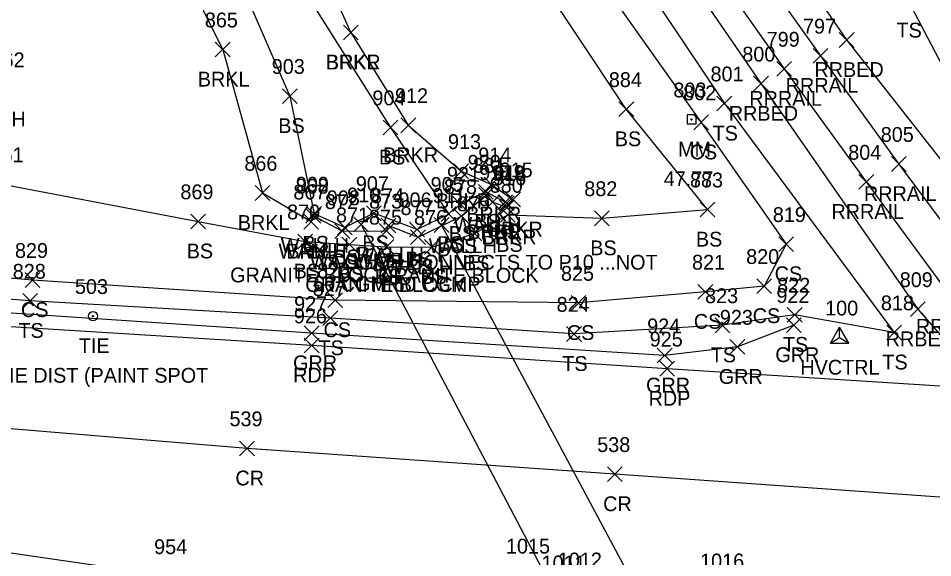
# Model space of a CAD drawing. Extents: x 1679360 to 1685861, y 903420 to 905946.
# Drawn here: x 1679676.5 to 1679800, y 904022.2 to 904095.2 of the extents above; entities that cross this region are included whole.
import ezdxf

# ---------------------------------------------------------------- set-up
doc = ezdxf.new("R2010")
doc.units = 0
for name, color, linetype in [('C_A', 7, 'Continuous'), ('C_C', 7, 'Continuous'), ('C_I', 7, 'Continuous'), ('CBP', 7, 'Continuous'), ('CPSM', 7, 'Continuous'), ('D_A', 7, 'Continuous'), ('D_C', 7, 'Continuous'), ('D_I', 7, 'Continuous'), ('D_TIC', 7, 'Continuous'), ('DCP', 7, 'Continuous'), ('DHW', 7, 'Continuous'), ('L_A', 7, 'Continuous'), ('L_I', 7, 'Continuous'), ('L_TIC', 7, 'Continuous'), ('LAWE', 7, 'Continuous'), ('LELB', 7, 'Continuous'), ('P_A', 7, 'Continuous'), ('P_I', 7, 'Continuous'), ('P_TIC', 7, 'Continuous'), ('PET', 7, 'Continuous'), ('PRC', 7, 'Continuous'), ('R_A', 7, 'Continuous'), ('R_I', 7, 'Continuous'), ('R_TIC', 7, 'Continuous'), ('RGR', 7, 'Continuous'), ('RR', 7, 'Continuous'), ('RRB', 7, 'Continuous'), ('S_A', 7, 'Continuous'), ('S_C', 7, 'Continuous'), ('S_I', 7, 'Continuous'), ('SRM', 7, 'Continuous')]:
    doc.layers.add(name, color=color, linetype=linetype)

msp = doc.modelspace()

# ---------------------------------------------------------------- linework, layer by layer
at = {"layer": 'CBP'}
for radius in [0.625, 0.0833]:
    msp.add_circle((1679686.58, 904054.87), radius, dxfattribs=at)
at = {"layer": 'CPSM'}
for p, q in [((1679786.2, 904051.23), (1679787.45, 904053.4)), ((1679788.7, 904051.23), (1679787.45, 904053.4)), ((1679787.45, 904051.96), (1679787.45, 904053.4)), ((1679786.2, 904051.23), (1679787.45, 904051.96)), ((1679786.2, 904051.23), (1679788.7, 904051.23)), ((1679787.45, 904051.96), (1679787.45, 904051.96)), ((1679787.45, 904051.96), (1679788.7, 904051.23))]:
    msp.add_line(p, q, dxfattribs=at)
at = {"layer": 'D_TIC'}
for points in [[(1679738.7, 904070.26), (1679740.7, 904072.26)], [(1679740.7, 904070.26), (1679738.7, 904072.26)], [(1679741.48, 904069.16), (1679743.48, 904071.16)], [(1679743.48, 904069.16), (1679741.48, 904071.16)], [(1679715.35, 904067.44), (1679717.35, 904069.44)], [(1679717.35, 904067.44), (1679715.35, 904069.44)], [(1679735.35, 904067.39), (1679737.35, 904069.39)], [(1679737.35, 904067.39), (1679735.35, 904069.39)], [(1679715.06, 904066.65), (1679717.06, 904068.65)], [(1679717.06, 904066.65), (1679715.06, 904068.65)], [(1679721.81, 904066.25), (1679723.81, 904068.25)], [(1679723.81, 904066.25), (1679721.81, 904068.25)], [(1679725.5, 904066.14), (1679727.5, 904068.14)], [(1679727.5, 904066.14), (1679725.5, 904068.14)], [(1679732.68, 904066.19), (1679734.68, 904068.19)], [(1679734.68, 904066.19), (1679732.68, 904068.19)], [(1679719.27, 904065.35), (1679721.27, 904067.35)], [(1679721.27, 904065.35), (1679719.27, 904067.35)], [(1679725.24, 904065.41), (1679727.24, 904067.41)], [(1679727.24, 904065.41), (1679725.24, 904067.41)], [(1679729.49, 904064.54), (1679731.49, 904066.54)], [(1679731.49, 904064.54), (1679729.49, 904066.54)]]:
    msp.add_lwpolyline(points, dxfattribs=at)
at = {"layer": 'DCP'}
for points in [[(1679722.81, 904067.25), (1679756.53, 904002.99)], [(1679733.68, 904067.19), (1679768.04, 904002.96)]]:
    msp.add_lwpolyline(points, dxfattribs=at)
at = {"layer": 'DHW'}
for points in [[(1679736.35, 904068.39), (1679739.7, 904071.26)], [(1679716.06, 904067.65), (1679716.35, 904068.44), (1679720.27, 904066.35)], [(1679726.24, 904066.41), (1679726.5, 904067.14), (1679730.49, 904065.54)]]:
    msp.add_lwpolyline(points, dxfattribs=at)
at = {"layer": 'L_TIC'}
for points in [[(1679720.41, 904092.23), (1679722.41, 904094.23)], [(1679722.41, 904092.23), (1679720.41, 904094.23)], [(1679720.41, 904092.23), (1679722.41, 904094.23)], [(1679722.41, 904092.23), (1679720.41, 904094.23)], [(1679703.1, 904089.92), (1679705.1, 904091.92)], [(1679705.1, 904089.92), (1679703.1, 904091.92)], [(1679712.17, 904083.63), (1679714.17, 904085.63)], [(1679714.17, 904083.63), (1679712.17, 904085.63)], [(1679770.88, 904082.62), (1679772.88, 904084.62)], [(1679772.88, 904082.62), (1679770.88, 904084.62)], [(1679757.63, 904081.85), (1679759.63, 904083.85)], [(1679759.63, 904081.85), (1679757.63, 904083.85)], [(1679728.18, 904079.68), (1679730.18, 904081.68)], [(1679730.18, 904079.68), (1679728.18, 904081.68)], [(1679767.75, 904080.07), (1679769.75, 904082.07)], [(1679769.75, 904080.07), (1679767.75, 904082.07)], [(1679725.77, 904079.38), (1679727.77, 904081.38)], [(1679727.77, 904079.38), (1679725.77, 904081.38)], [(1679735.33, 904073.46), (1679737.33, 904075.46)], [(1679737.33, 904073.46), (1679735.33, 904075.46)], [(1679739.42, 904071.67), (1679741.42, 904073.67)], [(1679741.42, 904071.67), (1679739.42, 904073.67)], [(1679708.49, 904070.53), (1679710.49, 904072.53)], [(1679710.49, 904070.53), (1679708.49, 904072.53)], [(1679738.65, 904070.68), (1679740.65, 904072.68)], [(1679740.65, 904070.68), (1679738.65, 904072.68)], [(1679735.2, 904069.04), (1679737.2, 904071.04)], [(1679737.2, 904069.04), (1679735.2, 904071.04)], [(1679739.55, 904069.27), (1679741.55, 904071.27)], [(1679741.55, 904069.27), (1679739.55, 904071.27)], [(1679741.25, 904069.27), (1679743.25, 904071.27)], [(1679743.25, 904069.27), (1679741.25, 904071.27)], [(1679741.48, 904068.57), (1679743.48, 904070.57)], [(1679743.48, 904068.57), (1679741.48, 904070.57)], [(1679742.32, 904069.64), (1679744.32, 904071.64)], [(1679744.32, 904069.64), (1679742.32, 904071.64)], [(1679715.44, 904067.71), (1679717.44, 904069.71)], [(1679717.44, 904067.71), (1679715.44, 904069.71)], [(1679715.44, 904067.71), (1679717.44, 904069.71)], [(1679717.44, 904067.71), (1679715.44, 904069.71)], [(1679723.53, 904067.78), (1679725.53, 904069.78)], [(1679725.53, 904067.78), (1679723.53, 904069.78)], [(1679733.63, 904067.68), (1679735.63, 904069.68)], [(1679735.63, 904067.68), (1679733.63, 904069.68)], [(1679735.35, 904067.39), (1679737.35, 904069.39)], [(1679737.35, 904067.39), (1679735.35, 904069.39)], [(1679741.62, 904067.56), (1679743.62, 904069.56)], [(1679743.62, 904067.56), (1679741.62, 904069.56)], [(1679768.59, 904068.28), (1679770.59, 904070.28)], [(1679770.59, 904068.28), (1679768.59, 904070.28)], [(1679699.8, 904066.68), (1679701.8, 904068.68)], [(1679701.8, 904066.68), (1679699.8, 904068.68)], [(1679715.06, 904066.65), (1679717.06, 904068.65)], [(1679717.06, 904066.65), (1679715.06, 904068.65)], [(1679754.32, 904067.1), (1679756.32, 904069.1)], [(1679756.32, 904067.1), (1679754.32, 904069.1)], [(1679719.27, 904065.35), (1679721.27, 904067.35)], [(1679721.27, 904065.35), (1679719.27, 904067.35)], [(1679719.61, 904065.87), (1679721.61, 904067.87)], [(1679721.61, 904065.87), (1679719.61, 904067.87)], [(1679725.24, 904065.41), (1679727.24, 904067.41)], [(1679727.24, 904065.41), (1679725.24, 904067.41)], [(1679729.36, 904065.6), (1679731.36, 904067.6)], [(1679731.36, 904065.6), (1679729.36, 904067.6)], [(1679737.12, 904065.05), (1679739.12, 904067.05)], [(1679739.12, 904065.05), (1679737.12, 904067.05)], [(1679714.25, 904063.96), (1679716.25, 904065.96)], [(1679716.25, 904063.96), (1679714.25, 904065.96)], [(1679729.49, 904064.54), (1679731.49, 904066.54)], [(1679731.49, 904064.54), (1679729.49, 904066.54)], [(1679779.23, 904063.6), (1679781.23, 904065.6)], [(1679781.23, 904063.6), (1679779.23, 904065.6)], [(1679720.21, 904063.56), (1679722.21, 904065.56)], [(1679722.21, 904063.56), (1679720.21, 904065.56)], [(1679725.22, 904063.25), (1679727.22, 904065.25)], [(1679727.22, 904063.25), (1679725.22, 904065.25)], [(1679731.36, 904063.22), (1679733.36, 904065.22)], [(1679733.36, 904063.22), (1679731.36, 904065.22)], [(1679677.41, 904058.75), (1679679.41, 904060.75)], [(1679679.41, 904058.75), (1679677.41, 904060.75)], [(1679776.26, 904057.93), (1679778.26, 904059.93)], [(1679778.26, 904057.93), (1679776.26, 904059.93)], [(1679768.31, 904057.16), (1679770.31, 904059.16)], [(1679770.31, 904057.16), (1679768.31, 904059.16)], [(1679677.1, 904055.93), (1679679.1, 904057.93)], [(1679679.1, 904055.93), (1679677.1, 904057.93)], [(1679718.29, 904056.03), (1679720.29, 904058.03)], [(1679720.29, 904056.03), (1679718.29, 904058.03)], [(1679751.16, 904055.65), (1679753.16, 904057.65)], [(1679753.16, 904055.65), (1679751.16, 904057.65)], [(1679780.37, 904054.05), (1679782.37, 904056.05)], [(1679782.37, 904054.05), (1679780.37, 904056.05)], [(1679717.64, 904053.59), (1679719.64, 904055.59)], [(1679719.64, 904053.59), (1679717.64, 904055.59)], [(1679770.63, 904052.63), (1679772.63, 904054.63)], [(1679772.63, 904052.63), (1679770.63, 904054.63)], [(1679750.57, 904051.46), (1679752.57, 904053.46)], [(1679752.57, 904051.46), (1679750.57, 904053.46)], [(1679793.81, 904051.66), (1679795.81, 904053.66)], [(1679795.81, 904051.66), (1679793.81, 904053.66)]]:
    msp.add_lwpolyline(points, dxfattribs=at)
at = {"layer": 'LAWE'}
for points in [[(1679721.41, 904093.23), (1679710.28, 904118.26), (1679642.61, 904214.69), (1679624.73, 904243.46), (1679599.05, 904283.15), (1679584.74, 904306.73)], [(1679693.3, 904112.54), (1679704.1, 904090.92), (1679709.49, 904071.53), (1679716.06, 904067.65)], [(1679721.41, 904093.23), (1679729.18, 904080.68), (1679736.33, 904074.46), (1679740.42, 904072.67), (1679743.32, 904070.64), (1679742.48, 904069.57), (1679740.55, 904070.27)]]:
    msp.add_lwpolyline(points, dxfattribs=at)
at = {"layer": 'LELB'}
for points in [[(1679957.35, 904067.57), (1679950.7, 904052.36), (1679948.48, 904046.41), (1679946.09, 904041.57), (1679931.01, 904039.98), (1679888.72, 904042.9), (1679856.91, 904046.05), (1679830.24, 904050.06), (1679823.69, 904055.74), (1679818.78, 904061.51), (1679813.5, 904065.59), (1679796.72, 904097.55), (1679771.59, 904129.9), (1679746.93, 904164.44), (1679719.12, 904199.21), (1679701.21, 904226.94), (1679680.19, 904259.65), (1679656.34, 904293.81), (1679636.23, 904329.88)], [(1679619.82, 904321.42), (1679641.86, 904284.96), (1679662.72, 904251.2), (1679682.47, 904216.95), (1679699.46, 904186.97), (1679725.72, 904150), (1679749.74, 904116.77), (1679771.88, 904083.62), (1679794.81, 904052.66), (1679781.37, 904055.05), (1679771.63, 904053.63), (1679751.57, 904052.46), (1679718.64, 904054.59), (1679678.1, 904056.93), (1679638.82, 904059.88), (1679596.67, 904062.24), (1679555.45, 904065.45), (1679516.04, 904068.29), (1679469.12, 904071.92)], [(1679613.72, 904318.48), (1679636.27, 904281.99), (1679658.68, 904248.53), (1679679.07, 904215.01), (1679696.37, 904185.6), (1679721.82, 904147.6), (1679745.3, 904114.19), (1679768.75, 904081.07), (1679780.23, 904064.6), (1679777.26, 904058.93), (1679769.31, 904058.16), (1679752.16, 904056.65), (1679719.29, 904057.03), (1679678.41, 904059.75), (1679639.22, 904063.11), (1679596.82, 904065.62), (1679556, 904068.19), (1679515.9, 904070.74), (1679469.14, 904074.52)], [(1679469.87, 904080.86), (1679506.34, 904080.86), (1679543.9, 904078.61), (1679576.91, 904079.34), (1679615.93, 904077.92), (1679644, 904075.64), (1679674.59, 904072.69), (1679700.8, 904067.68), (1679715.25, 904064.96), (1679721.21, 904064.56), (1679726.22, 904064.25), (1679732.36, 904064.22), (1679738.12, 904066.05), (1679742.62, 904068.56), (1679755.32, 904068.1), (1679769.59, 904069.28), (1679758.63, 904082.85), (1679744.91, 904103.49), (1679726.51, 904128.69), (1679708.52, 904157.77), (1679684.84, 904191.6)], [(1679704.38, 904115.88), (1679726.77, 904080.38), (1679734.63, 904068.68), (1679730.36, 904066.6), (1679724.53, 904068.78), (1679720.61, 904066.87), (1679716.44, 904068.71)], [(1679700.75, 904113.26), (1679713.17, 904084.63), (1679716.44, 904068.71)], [(1679742.25, 904070.27), (1679739.65, 904071.68), (1679736.2, 904070.04)], [(1679730.49, 904065.54), (1679736.35, 904068.39)], [(1679720.27, 904066.35), (1679726.24, 904066.41)]]:
    msp.add_lwpolyline(points, dxfattribs=at)
at = {"layer": 'P_TIC'}
for points in [[(1679715.13, 904049.9), (1679717.13, 904051.9)], [(1679717.13, 904049.9), (1679715.13, 904051.9)], [(1679763.15, 904046.76), (1679765.15, 904048.76)], [(1679765.15, 904046.76), (1679763.15, 904048.76)], [(1679706.39, 904035.98), (1679708.39, 904037.98)], [(1679708.39, 904035.98), (1679706.39, 904037.98)], [(1679756.07, 904032.5), (1679758.07, 904034.5)], [(1679758.07, 904032.5), (1679756.07, 904034.5)]]:
    msp.add_lwpolyline(points, dxfattribs=at)
at = {"layer": 'PET'}
for points in [[(1680210.84, 904017.73), (1680154.55, 904022.58), (1680102.27, 904026.43), (1680051.74, 904029.42), (1680001.13, 904032.43), (1679941.04, 904036.26), (1679894.06, 904039.28), (1679848.46, 904042.23), (1679824.08, 904043.91), (1679814.8, 904045.29), (1679808.83, 904044.91), (1679764.15, 904047.76), (1679716.13, 904050.9), (1679671, 904053.69), (1679626.09, 904056.57), (1679579.85, 904059.36), (1679535.31, 904061.44), (1679496.62, 904064.3), (1679468.44, 904066.43)], [(1679464.45, 904041.77), (1679494.85, 904039.78), (1679533.66, 904036.86), (1679564.76, 904034.75), (1679595.94, 904030.8), (1679627.79, 904028.13), (1679661.16, 904024.92), (1679697.2, 904019.69), (1679719.42, 904015.4), (1679737.48, 904014.62), (1679744.58, 904019.77), (1679770.86, 904017.76), (1679789.63, 904016.53)]]:
    msp.add_lwpolyline(points, dxfattribs=at)
at = {"layer": 'PRC'}
msp.add_lwpolyline([(1680209.65, 904002.04), (1680152.97, 904005.78), (1680100.29, 904009.57), (1680049.21, 904012.91), (1679999.46, 904016.39), (1679940.5, 904020.99), (1679893.64, 904024.04), (1679847.03, 904027.44), (1679827.53, 904028.69), (1679808.61, 904029.86), (1679757.07, 904033.5), (1679707.39, 904036.98), (1679666.22, 904040.39), (1679623.03, 904043.25), (1679581.59, 904046.25), (1679534.87, 904049.67), (1679494.87, 904052.55), (1679467.34, 904054.68)], dxfattribs=at)
at = {"layer": 'R_TIC'}
for points in [[(1679787.39, 904091.22), (1679789.39, 904093.22)], [(1679789.39, 904091.22), (1679787.39, 904093.22)], [(1679783.87, 904089.08), (1679785.87, 904091.08)], [(1679785.87, 904089.08), (1679783.87, 904091.08)], [(1679778.96, 904087.31), (1679780.96, 904089.31)], [(1679780.96, 904087.31), (1679778.96, 904089.31)], [(1679775.83, 904085.3), (1679777.83, 904087.3)], [(1679777.83, 904085.3), (1679775.83, 904087.3)], [(1679794.44, 904074.44), (1679796.44, 904076.44)], [(1679796.44, 904074.44), (1679794.44, 904076.44)], [(1679790.05, 904072.02), (1679792.05, 904074.02)], [(1679792.05, 904072.02), (1679790.05, 904074.02)], [(1679797.02, 904054.8), (1679799.02, 904056.8)], [(1679799.02, 904054.8), (1679797.02, 904056.8)], [(1679780.27, 904052.66), (1679782.27, 904054.66)], [(1679782.27, 904052.66), (1679780.27, 904054.66)], [(1679715.12, 904051.56), (1679717.12, 904053.56)], [(1679717.12, 904051.56), (1679715.12, 904053.56)], [(1679772.63, 904049.71), (1679774.63, 904051.71)], [(1679774.63, 904049.71), (1679772.63, 904051.71)], [(1679762.81, 904048.54), (1679764.81, 904050.54)], [(1679764.81, 904048.54), (1679762.81, 904050.54)]]:
    msp.add_lwpolyline(points, dxfattribs=at)
at = {"layer": 'RGR'}
msp.add_lwpolyline([(1679781.27, 904053.66), (1679773.63, 904050.71), (1679763.81, 904049.54), (1679716.12, 904052.56), (1679671.48, 904055.53), (1679626.4, 904058.62), (1679580.17, 904061.85), (1679535.72, 904064.7), (1679497.22, 904067.59), (1679469, 904069.72)], dxfattribs=at)
at = {"layer": 'RR'}
for points in [[(1679726.81, 904174.45), (1679738.46, 904156.9), (1679751.84, 904137.33), (1679761.54, 904123.21), (1679774.27, 904104.96), (1679784.87, 904090.08), (1679795.44, 904075.44), (1679806.42, 904060.67), (1679817.7, 904045.88), (1679831.29, 904028.45), (1679844.1, 904012.06)], [(1679722.86, 904171.49), (1679733.8, 904154.92), (1679747.61, 904134.64), (1679756.68, 904121.56), (1679770.36, 904101.93), (1679779.96, 904088.31), (1679791.05, 904073.02), (1679802.46, 904057.5), (1679811.73, 904045.41), (1679824.64, 904028.72), (1679837.34, 904012.39)]]:
    msp.add_lwpolyline(points, dxfattribs=at)
at = {"layer": 'RRB'}
for points in [[(1679633.2, 904329.89), (1679656.09, 904293.31), (1679676.78, 904259.06), (1679698.16, 904224.73), (1679716.55, 904197.16), (1679742.3, 904159.89), (1679765.39, 904125.58), (1679788.39, 904092.22), (1679811.33, 904062.99), (1679819.97, 904050.18)], [(1679622.51, 904322.69), (1679644.95, 904286.47), (1679665.07, 904252.34), (1679687.42, 904219.26), (1679705.66, 904190.77), (1679730.04, 904152.75), (1679754.13, 904119.39), (1679776.83, 904086.3), (1679798.02, 904055.8), (1679804.41, 904048.47)]]:
    msp.add_lwpolyline(points, dxfattribs=at)
at = {"layer": 'SRM'}
for p, q in [((1679768.08, 904082.11), (1679766.83, 904082.11)), ((1679766.83, 904082.11), (1679766.83, 904080.86)), ((1679768.08, 904082.11), (1679766.83, 904082.11)), ((1679766.83, 904082.11), (1679766.83, 904080.86)), ((1679768.08, 904080.86), (1679768.08, 904082.11)), ((1679768.08, 904080.86), (1679768.08, 904082.11)), ((1679766.83, 904080.86), (1679768.08, 904080.86)), ((1679766.83, 904080.86), (1679768.08, 904080.86))]:
    msp.add_line(p, q, dxfattribs=at)
msp.add_circle((1679767.43, 904081.45), 0.0833, dxfattribs=at)

# ---------------------------------------------------------------- texts
at = {"layer": 'C_A'}
for s, p in [('TIE', (1679684.66, 904049.87)), ('HVCTRL', (1679782.14, 904046.96))]:
    msp.add_text(s, height=2, dxfattribs=at).set_placement(p)
at = {"layer": 'C_C'}
msp.add_text('46.53 IS TIE DIST (PAINT SPOT', height=2, dxfattribs=at).set_placement((1679662.91, 904045.87))
at = {"layer": 'C_I'}
for s, p in [('503', (1679684.14, 904057.87)), ('100', (1679785.49, 904054.96))]:
    msp.add_text(s, height=2, dxfattribs=at).set_placement(p)
at = {"layer": 'D_A'}
for s, p in [('WALLH', (1679735.29, 904066.26)), ('P', (1679741.86, 904065.16)), ('WALLH', (1679711.65, 904062.65)), ('WALLH', (1679711.95, 904063.44)), ('WALLH', (1679731.94, 904063.39)), ('WALLH', (1679715.86, 904061.35)), ('WALLH', (1679721.83, 904061.41)), ('WALLH', (1679722.09, 904062.14)), ('P', (1679722.18, 904062.25)), ('P', (1679733.06, 904062.19)), ('WALLH', (1679726.08, 904060.54))]:
    msp.add_text(s, height=2, dxfattribs=at).set_placement(p)
at = {"layer": 'D_C'}
for s, p in [('18 CGMP CONNECTS TO P10 ...NOT', (1679716.79, 904061.16)), ('GRANITE BLOCK', (1679705.11, 904059.44)), ('GRANITE BLOCK', (1679725.1, 904059.39)), ('GRANITE BLOCK', (1679715.26, 904058.14)), ('60 CGMP', (1679716.33, 904058.25)), ('60 CGMP', (1679727.2, 904058.19))]:
    msp.add_text(s, height=2, dxfattribs=at).set_placement(p)
at = {"layer": 'D_I'}
for s, p in [('881', (1679737.9, 904074.26)), ('918', (1679740.68, 904073.16)), ('868', (1679713.95, 904071.44)), ('878', (1679733.99, 904071.39)), ('867', (1679713.65, 904070.65)), ('910', (1679720.92, 904070.25)), ('874', (1679724.14, 904070.14)), ('911', (1679732.46, 904070.19)), ('872', (1679717.91, 904069.35)), ('873', (1679723.88, 904069.41)), ('877', (1679728.13, 904068.54))]:
    msp.add_text(s, height=2, dxfattribs=at).set_placement(p)
at = {"layer": 'L_A'}
for s, p in [('TS', (1679795.13, 904092.55)), ('BRKR', (1679718, 904088.23)), ('BRKL', (1679718.06, 904088.23)), ('BRKL', (1679700.74, 904085.92)), ('SH', (1679673.77, 904080.53)), ('BS', (1679711.61, 904079.63)), ('TS', (1679770.29, 904078.62)), ('BS', (1679757.07, 904077.85)), ('CS', (1679767.19, 904076.07)), ('BS', (1679725.21, 904075.38)), ('BRKR', (1679725.77, 904075.68)), ('BRKR', (1679732.92, 904069.46)), ('BRKR', (1679737.01, 904067.67)), ('BRKL', (1679706.14, 904066.53)), ('BS', (1679738.09, 904066.68)), ('BS', (1679734.64, 904065.04)), ('BRKR', (1679737.14, 904065.27)), ('BRKR', (1679739.91, 904065.64)), ('BS', (1679740.69, 904065.27)), ('BS', (1679714.88, 904063.71)), ('BS', (1679714.88, 904063.71)), ('BS', (1679722.97, 904063.78)), ('BS', (1679733.07, 904063.68)), ('BRKR', (1679739.07, 904064.57)), ('BS', (1679768.03, 904064.28)), ('BS', (1679699.24, 904062.68)), ('BRKL', (1679712.7, 904062.65)), ('CS', (1679734.79, 904063.39)), ('BS', (1679741.06, 904063.56)), ('BS', (1679753.76, 904063.1)), ('CS', (1679718.71, 904061.35)), ('BS', (1679719.05, 904061.87)), ('CS', (1679724.68, 904061.41)), ('BS', (1679728.8, 904061.6)), ('BS', (1679713.69, 904059.96)), ('CS', (1679728.93, 904060.54)), ('BS', (1679736.56, 904061.05)), ('BS', (1679719.65, 904059.56)), ('BS', (1679724.66, 904059.25)), ('BS', (1679730.8, 904059.22)), ('CS', (1679778.67, 904059.6)), ('CS', (1679676.85, 904054.75)), ('CS', (1679775.71, 904053.93)), ('CS', (1679767.75, 904053.16)), ('TS', (1679676.51, 904051.93)), ('CS', (1679717.73, 904052.03)), ('CS', (1679750.6, 904051.65)), ('TS', (1679779.78, 904050.05)), ('TS', (1679717.05, 904049.59)), ('TS', (1679770.04, 904048.63)), ('TS', (1679793.22, 904047.66)), ('TS', (1679749.98, 904047.46))]:
    msp.add_text(s, height=2, dxfattribs=at).set_placement(p)
at = {"layer": 'L_I'}
for s, p in [('865', (1679701.69, 904093.92)), ('862', (1679672.88, 904088.53)), ('903', (1679710.73, 904087.63)), ('884', (1679756.27, 904085.85)), ('801', (1679770.01, 904086.62)), ('904', (1679724.33, 904083.38)), ('912', (1679727.38, 904083.68)), ('802', (1679766.31, 904084.07)), ('913', (1679734.54, 904077.46)), ('861', (1679672.74, 904075.69)), ('920', (1679737.2, 904074.68)), ('914', (1679738.63, 904075.67)), ('866', (1679707.03, 904074.53)), ('915', (1679741.52, 904073.64)), ('921', (1679734.4, 904073.04)), ('917', (1679738.76, 904073.27)), ('919', (1679740.44, 904073.27)), ('916', (1679740.63, 904072.57)), ('883', (1679767.23, 904072.28)), ('909', (1679713.99, 904071.71)), ('909', (1679713.99, 904071.71)), ('907', (1679722.09, 904071.78)), ('905', (1679732.19, 904071.68)), ('878', (1679733.99, 904071.39)), ('880', (1679740.17, 904071.56)), ('882', (1679752.95, 904071.1)), ('869', (1679698.39, 904070.68)), ('867', (1679713.65, 904070.65)), ('908', (1679718.17, 904069.87)), ('872', (1679717.91, 904069.35)), ('873', (1679723.88, 904069.41)), ('906', (1679727.86, 904069.6)), ('877', (1679728.13, 904068.54)), ('879', (1679735.75, 904069.05)), ('870', (1679712.8, 904067.96)), ('871', (1679719.41, 904067.56)), ('819', (1679778.42, 904067.6)), ('875', (1679723.86, 904067.25)), ('876', (1679729.95, 904067.22)), ('829', (1679676.04, 904062.75)), ('821', (1679767.51, 904061.16)), ('820', (1679774.82, 904061.93)), ('828', (1679675.74, 904059.93)), ('826', (1679716.87, 904060.03)), ('825', (1679749.8, 904059.65)), ('827', (1679716.27, 904057.59)), ('822', (1679779.01, 904058.05)), ('823', (1679769.27, 904056.63)), ('824', (1679749.21, 904055.46)), ('818', (1679793.02, 904055.66))]:
    msp.add_text(s, height=2, dxfattribs=at).set_placement(p)
at = {"layer": 'P_A'}
for s, p in [('RDP', (1679713.62, 904045.9)), ('RDP', (1679761.64, 904042.76)), ('CR', (1679705.82, 904031.98)), ('CR', (1679755.5, 904028.5))]:
    msp.add_text(s, height=2, dxfattribs=at).set_placement(p)
at = {"layer": 'P_I'}
for s, p in [('926', (1679713.72, 904053.9)), ('925', (1679761.79, 904050.76)), ('539', (1679705.02, 904039.98)), ('538', (1679754.7, 904036.5)), ('954', (1679694.84, 904022.69)), ('1015', (1679742.37, 904022.77)), ('1016', (1679768.6, 904020.76))]:
    msp.add_text(s, height=2, dxfattribs=at).set_placement(p)
at = {"layer": 'R_A'}
for s, p in [('RRBED', (1679784.04, 904087.22)), ('RRRAIL', (1679780.16, 904085.08)), ('RRRAIL', (1679775.25, 904083.31)), ('RRBED', (1679772.47, 904081.3)), ('RRRAIL', (1679790.73, 904070.44)), ('RRRAIL', (1679786.34, 904068.02)), ('RRRAIL', (1679797.75, 904052.5)), ('RRBED', (1679793.67, 904050.8)), ('GRR', (1679713.61, 904047.56)), ('GRR', (1679778.76, 904048.66)), ('GRR', (1679771.12, 904045.71)), ('GRR', (1679761.3, 904044.54))]:
    msp.add_text(s, height=2, dxfattribs=at).set_placement(p)
at = {"layer": 'R_I'}
for s, p in [('797', (1679782.5, 904093.08)), ('799', (1679777.59, 904091.31)), ('800', (1679774.3, 904089.3)), ('805', (1679793, 904078.44)), ('804', (1679788.61, 904076.02)), ('809', (1679795.57, 904058.8)), ('922', (1679778.91, 904056.66)), ('927', (1679713.75, 904055.56)), ('923', (1679771.27, 904053.71)), ('924', (1679761.45, 904052.54)), ('1011', (1679747.18, 904020.49)), ('1012', (1679749.38, 904020.89))]:
    msp.add_text(s, height=2, dxfattribs=at).set_placement(p)
at = {"layer": 'S_A'}
msp.add_text('MM', height=2, dxfattribs=at).set_placement((1679765.62, 904076.45))
at = {"layer": 'S_C'}
msp.add_text('47.77', height=2, dxfattribs=at).set_placement((1679763.68, 904072.45))
at = {"layer": 'S_I'}
msp.add_text('803', height=2, dxfattribs=at).set_placement((1679764.99, 904084.45))

doc.saveas('drawing.dxf')
